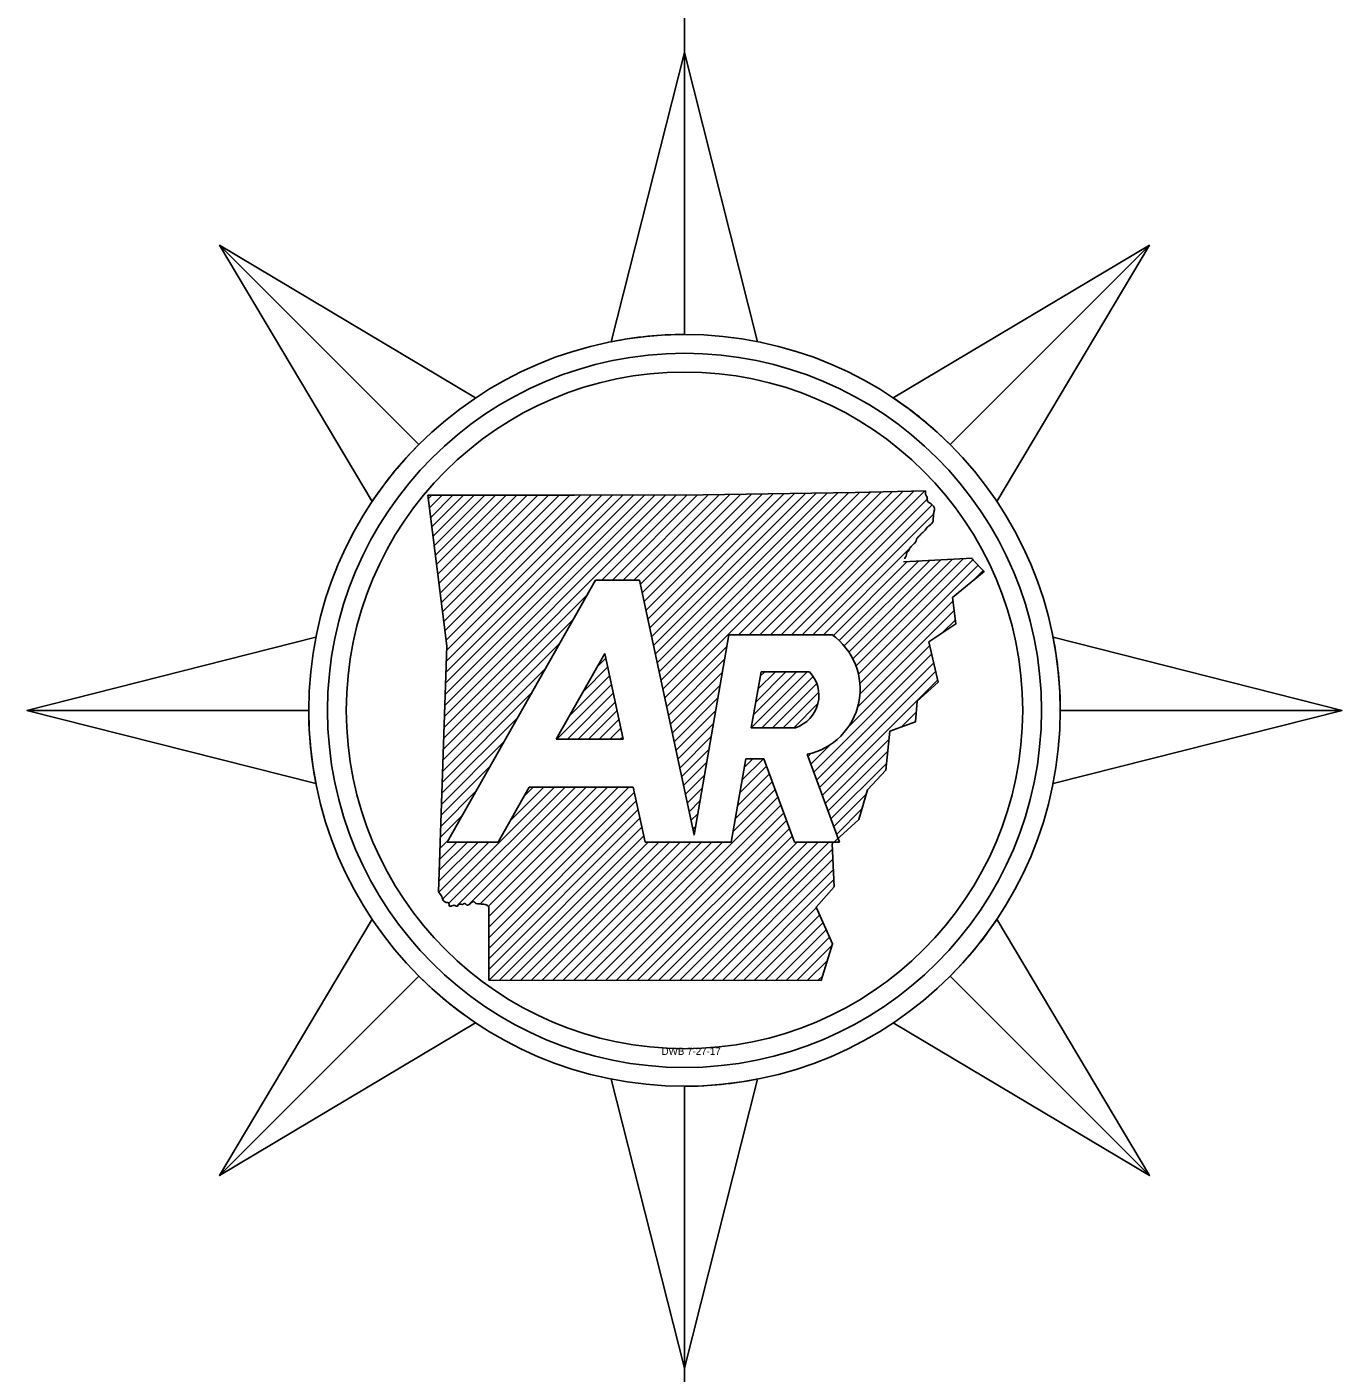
# Model space of a CAD drawing. Extents: x 1368042 to 1371376, y 380392 to 382637.
# Drawn here: x 1370557.8 to 1370680.3, y 381249.8 to 381375.2 of the extents above; entities that cross this region are included whole.
import ezdxf

# ---------------------------------------------------------------- set-up
doc = ezdxf.new("R2010")
doc.units = 0
doc.layers.add('R_Draft', color=7, linetype='Continuous')
doc.layers.add('R_Water Annot', color=7, linetype='Continuous')

msp = doc.modelspace()

# ---------------------------------------------------------------- linework, layer by layer
at = {"layer": 'R_Draft'}
for p, q in [((1370619.08, 381488.53), (1370619.08, 381350.36)), ((1370619.08, 381372.78), (1370612.26, 381345.86)), ((1370619.08, 381346.53), (1370619.08, 381372.78)), ((1370575.77, 381354.84), (1370594.33, 381336.28)), ((1370594.33, 381336.28), (1370575.77, 381354.84)), ((1370575.77, 381354.84), (1370589.98, 381330.99)), ((1370662.39, 381354.84), (1370638.53, 381340.63)), ((1370643.83, 381336.28), (1370662.39, 381354.84)), ((1370643.83, 381336.28), (1370662.39, 381354.84)), ((1370596.97, 381299.27), (1370610.78, 381323.66)), ((1370610.78, 381323.66), (1370614.89, 381323.66)), ((1370623.22, 381318.57), (1370632.81, 381318.57)), ((1370680.33, 381311.53), (1370653.41, 381318.35)), ((1370607.13, 381308.85), (1370611.65, 381316.82)), ((1370626.21, 381315.13), (1370630.71, 381315.13)), ((1370557.83, 381311.53), (1370584.08, 381311.53)), ((1370584.08, 381311.53), (1370557.83, 381311.53)), ((1370557.83, 381311.53), (1370584.75, 381304.72)), ((1370654.08, 381311.53), (1370680.33, 381311.53)), ((1370654.08, 381311.53), (1370680.33, 381311.53)), ((1370625.3, 381309.92), (1370629.41, 381309.92)), ((1370607.13, 381308.85), (1370613.36, 381308.85)), ((1370630.52, 381307.44), (1370633.53, 381299.27)), ((1370626.46, 381307.03), (1370624.79, 381307.03)), ((1370629.32, 381299.27), (1370626.46, 381307.03)), ((1370604.61, 381304.39), (1370601.71, 381299.27)), ((1370614.31, 381304.39), (1370604.61, 381304.39)), ((1370601.71, 381299.27), (1370596.97, 381299.27)), ((1370623.44, 381299.27), (1370615.41, 381299.27)), ((1370633.53, 381299.27), (1370629.32, 381299.27)), ((1370662.39, 381268.22), (1370648.17, 381292.08)), ((1370575.77, 381268.22), (1370594.33, 381286.79)), ((1370594.33, 381286.79), (1370575.77, 381268.22)), ((1370643.83, 381286.79), (1370662.39, 381268.22)), ((1370643.83, 381286.79), (1370662.39, 381268.22)), ((1370575.77, 381268.22), (1370599.62, 381282.44)), ((1370619.08, 381250.28), (1370625.89, 381277.2)), ((1370619.08, 381276.53), (1370619.08, 381276.54)), ((1370619.08, 381276.53), (1370619.08, 381164.49)), ((1370619.08, 381276.53), (1370619.08, 381250.28))]:
    msp.add_line(p, q, dxfattribs=at)
for points in [[(1370612.26, 381345.86), (1370619.08, 381372.78), (1370625.89, 381345.86)], [(1370589.98, 381330.99), (1370575.77, 381354.84), (1370599.62, 381340.63)], [(1370638.53, 381340.63), (1370662.39, 381354.84), (1370648.17, 381330.99)], [(1370595.18, 381331.57), (1370608.84, 381331.56), (1370620.83, 381331.59), (1370634.97, 381331.81), (1370641.52, 381331.96)], [(1370596.17, 381294.62), (1370596.93, 381317.53), (1370595.18, 381331.57)], [(1370645.81, 381325.68), (1370646.99, 381324.45), (1370644.05, 381322.03), (1370644.36, 381319.58), (1370641.84, 381317.91), (1370642.7, 381314.16), (1370640.75, 381312.38), (1370640.58, 381310.45), (1370638.21, 381309.59), (1370637.84, 381305.95), (1370636.14, 381304.13), (1370635.32, 381301.38), (1370632.84, 381299.11), (1370633.03, 381295.11), (1370631.34, 381293.22), (1370632.88, 381289.79), (1370631.81, 381286.37)], [(1370639.49, 381325.36), (1370645.9, 381325.69)], [(1370614.89, 381323.66), (1370619.97, 381299.93), (1370623.22, 381318.57)], [(1370584.75, 381304.72), (1370557.83, 381311.53), (1370584.75, 381318.35)], [(1370653.41, 381318.35), (1370680.33, 381311.53), (1370653.41, 381304.72)], [(1370611.65, 381316.82), (1370613.36, 381308.85)], [(1370625.3, 381309.92), (1370626.21, 381315.13)], [(1370624.79, 381307.03), (1370623.44, 381299.27)], [(1370615.41, 381299.27), (1370614.31, 381304.39)], [(1370631.81, 381286.37), (1370600.86, 381286.42), (1370600.84, 381293.26)], [(1370599.62, 381282.44), (1370575.77, 381268.22), (1370589.98, 381292.08)], [(1370648.17, 381292.08), (1370662.39, 381268.22), (1370638.53, 381282.44)], [(1370625.89, 381277.2), (1370619.08, 381250.28), (1370612.26, 381277.2)]]:
    msp.add_lwpolyline(points, dxfattribs=at)
for radius in [35, 31.5]:
    msp.add_circle((1370619.08, 381311.53), radius, dxfattribs=at)
for centre, radius, start, end in [((1370619.08, 381311.53), 35, 90, 101.2291), ((1370619.08, 381311.53), 35, 45, 56.2291), ((1370619.08, 381311.53), 35, 135, 146.2291), ((1370629.24, 381313.51), 6.2, 281.8626, 54.8705), ((1370619.08, 381311.53), 35, 0, 11.2291), ((1370628.43, 381312.93), 3.17, 288.1268, 43.8902), ((1370619.08, 381311.53), 35, 180, 191.2291), ((1370619.08, 381311.53), 35, 315, 326.2291), ((1370619.08, 381311.53), 35, 225, 236.2291), ((1370619.08, 381311.53), 35, 270, 281.2291)]:
    msp.add_arc(centre, radius, start, end, dxfattribs=at)
for points in [[(1370641.52, 381331.96), (1370641.56, 381331.59), (1370641.68, 381331.39), (1370641.7, 381331.04), (1370641.84, 381330.89), (1370642.09, 381330.73), (1370642.3, 381330.49), (1370642.36, 381330.2), (1370642.29, 381329.91), (1370642.27, 381329.58), (1370642.24, 381329.29), (1370642.19, 381329.03), (1370641.98, 381328.82), (1370641.79, 381328.66), (1370641.61, 381328.49), (1370641.49, 381328.3), (1370641.27, 381328.1), (1370641.05, 381327.89), (1370640.87, 381327.7), (1370640.69, 381327.46), (1370640.61, 381327.2), (1370640.41, 381327.02), (1370640.26, 381326.85), (1370640.06, 381326.62), (1370639.96, 381326.39), (1370639.76, 381326.13), (1370639.72, 381325.88), (1370639.59, 381325.67), (1370639.59, 381325.64)], [(1370600.84, 381293.26), (1370600.88, 381293.24), (1370600.72, 381293.35), (1370600.5, 381293.46), (1370600.25, 381293.48), (1370599.94, 381293.52), (1370599.68, 381293.54), (1370599.41, 381293.72), (1370599.12, 381293.54), (1370598.8, 381293.4), (1370598.61, 381293.55), (1370598.37, 381293.45), (1370598.2, 381293.5), (1370597.9, 381293.3), (1370597.62, 381293.38), (1370597.42, 381293.32), (1370597.17, 381293.33), (1370597.12, 381293.61), (1370596.87, 381293.65), (1370596.66, 381293.77), (1370596.52, 381294.07), (1370596.42, 381294.3), (1370596.17, 381294.62)]]:
    msp.add_spline(points, degree=3, dxfattribs=at)
at = {"layer": 'R_Water Annot'}
for p, q in [((1370595.22, 381331.26), (1370595.53, 381331.57)), ((1370595.33, 381330.38), (1370596.52, 381331.57)), ((1370595.44, 381329.5), (1370597.51, 381331.57)), ((1370595.55, 381328.62), (1370598.5, 381331.57)), ((1370595.66, 381327.74), (1370599.49, 381331.57)), ((1370595.77, 381326.86), (1370600.48, 381331.57)), ((1370595.88, 381325.98), (1370601.47, 381331.57)), ((1370595.99, 381325.1), (1370602.46, 381331.56)), ((1370596.1, 381324.22), (1370603.45, 381331.56)), ((1370596.21, 381323.34), (1370604.43, 381331.56)), ((1370596.32, 381322.46), (1370605.42, 381331.56)), ((1370596.43, 381321.58), (1370606.41, 381331.56)), ((1370596.54, 381320.7), (1370607.4, 381331.56)), ((1370596.65, 381319.82), (1370608.39, 381331.56)), ((1370596.68, 381309.95), (1370618.31, 381331.58)), ((1370596.71, 381310.97), (1370617.32, 381331.58)), ((1370596.75, 381312), (1370616.33, 381331.58)), ((1370596.76, 381318.94), (1370609.38, 381331.56)), ((1370596.78, 381313.02), (1370615.34, 381331.57)), ((1370596.82, 381314.05), (1370614.34, 381331.57)), ((1370596.85, 381315.07), (1370613.35, 381331.57)), ((1370596.87, 381318.06), (1370610.38, 381331.56)), ((1370596.88, 381316.09), (1370612.36, 381331.57)), ((1370596.92, 381317.12), (1370611.37, 381331.57)), ((1370611.38, 381323.66), (1370619.3, 381331.58)), ((1370612.37, 381323.66), (1370620.3, 381331.59)), ((1370613.36, 381323.66), (1370621.29, 381331.59)), ((1370614.35, 381323.66), (1370622.3, 381331.61)), ((1370614.97, 381323.29), (1370623.31, 381331.62)), ((1370615.14, 381322.47), (1370624.31, 381331.64)), ((1370615.32, 381321.66), (1370625.32, 381331.66)), ((1370615.49, 381320.84), (1370626.32, 381331.67)), ((1370615.67, 381320.03), (1370627.33, 381331.69)), ((1370615.84, 381319.21), (1370628.33, 381331.7)), ((1370616.01, 381318.39), (1370629.34, 381331.72)), ((1370616.19, 381317.58), (1370630.34, 381331.73)), ((1370616.36, 381316.76), (1370631.35, 381331.75)), ((1370616.54, 381315.95), (1370632.36, 381331.77)), ((1370616.71, 381315.13), (1370633.36, 381331.78)), ((1370616.89, 381314.32), (1370634.37, 381331.8)), ((1370617.06, 381313.5), (1370635.38, 381331.82)), ((1370617.24, 381312.69), (1370636.39, 381331.84)), ((1370624.11, 381318.57), (1370637.4, 381331.86)), ((1370625.1, 381318.57), (1370638.42, 381331.89)), ((1370626.09, 381318.57), (1370639.43, 381331.91)), ((1370627.08, 381318.57), (1370640.44, 381331.93)), ((1370628.07, 381318.57), (1370641.46, 381331.96)), ((1370629.06, 381318.57), (1370641.68, 381331.19)), ((1370630.05, 381318.57), (1370642.15, 381330.68)), ((1370631.04, 381318.57), (1370642.28, 381329.81)), ((1370632.03, 381318.57), (1370640.02, 381326.56)), ((1370632.93, 381318.48), (1370639.83, 381325.38)), ((1370633.47, 381318.03), (1370640.87, 381325.43)), ((1370633.96, 381317.53), (1370641.92, 381325.49)), ((1370634.38, 381316.96), (1370642.96, 381325.54)), ((1370634.75, 381316.34), (1370644, 381325.59)), ((1370635.05, 381315.65), (1370645.05, 381325.65)), ((1370635.28, 381314.89), (1370645.99, 381325.6)), ((1370635.42, 381314.04), (1370646.45, 381325.07)), ((1370646.01, 381323.64), (1370646.91, 381324.54)), ((1370596.65, 381308.93), (1370610, 381322.28)), ((1370635.42, 381313.05), (1370644.09, 381321.72)), ((1370596.61, 381307.9), (1370608.71, 381320)), ((1370635.21, 381311.85), (1370644.2, 381320.84)), ((1370643.09, 381318.74), (1370644.31, 381319.96)), ((1370596.58, 381306.88), (1370607.42, 381317.72)), ((1370617.41, 381311.87), (1370623.03, 381317.49)), ((1370634.35, 381310), (1370641.92, 381317.57)), ((1370610.95, 381315.58), (1370611.75, 381316.38)), ((1370617.59, 381311.06), (1370622.82, 381316.29)), ((1370631.13, 381305.79), (1370642.1, 381316.76)), ((1370631.39, 381305.07), (1370642.29, 381315.96)), ((1370596.54, 381305.85), (1370606.13, 381315.44)), ((1370608.36, 381311.02), (1370612.09, 381314.75)), ((1370609.66, 381313.3), (1370611.92, 381315.56)), ((1370617.76, 381310.24), (1370622.61, 381315.09)), ((1370625.3, 381309.92), (1370630.51, 381315.13)), ((1370625.51, 381311.12), (1370629.52, 381315.13)), ((1370625.72, 381312.31), (1370628.53, 381315.13)), ((1370625.92, 381313.51), (1370627.54, 381315.13)), ((1370626.13, 381314.71), (1370626.55, 381315.13)), ((1370626.29, 381309.92), (1370631.06, 381314.69)), ((1370631.66, 381304.34), (1370642.47, 381315.15)), ((1370607.18, 381308.85), (1370612.27, 381313.93)), ((1370617.93, 381309.42), (1370622.4, 381313.89)), ((1370627.28, 381309.92), (1370631.4, 381314.04)), ((1370631.93, 381303.62), (1370642.66, 381314.35)), ((1370596.51, 381304.83), (1370604.84, 381313.16)), ((1370608.17, 381308.85), (1370612.44, 381313.12)), ((1370609.16, 381308.85), (1370612.62, 381312.3)), ((1370618.11, 381308.61), (1370622.19, 381312.69)), ((1370628.27, 381309.92), (1370631.58, 381313.23)), ((1370629.26, 381309.92), (1370631.5, 381312.16)), ((1370610.15, 381308.85), (1370612.79, 381311.49)), ((1370618.28, 381307.79), (1370621.98, 381311.49)), ((1370639.27, 381309.98), (1370640.66, 381311.36)), ((1370596.48, 381303.81), (1370603.54, 381310.87)), ((1370611.14, 381308.85), (1370612.97, 381310.67)), ((1370612.13, 381308.85), (1370613.14, 381309.86)), ((1370618.46, 381306.98), (1370621.77, 381310.3)), ((1370596.44, 381302.78), (1370602.25, 381308.59)), ((1370613.12, 381308.85), (1370613.32, 381309.04)), ((1370618.63, 381306.16), (1370621.57, 381309.1)), ((1370630.86, 381306.51), (1370632.74, 381308.4)), ((1370632.2, 381302.9), (1370638.13, 381308.84)), ((1370618.81, 381305.35), (1370621.36, 381307.9)), ((1370630.59, 381307.23), (1370630.89, 381307.54)), ((1370632.46, 381302.17), (1370638.02, 381307.73)), ((1370596.41, 381301.76), (1370600.96, 381306.31)), ((1370618.98, 381304.53), (1370621.15, 381306.7)), ((1370624.24, 381303.85), (1370626.72, 381306.33)), ((1370624.45, 381305.05), (1370626.43, 381307.03)), ((1370624.66, 381306.25), (1370625.44, 381307.03)), ((1370632.73, 381301.45), (1370637.91, 381306.63)), ((1370619.16, 381303.72), (1370620.94, 381305.5)), ((1370623.82, 381301.45), (1370627.25, 381304.88)), ((1370624.03, 381302.65), (1370626.98, 381305.6)), ((1370596.37, 381300.73), (1370599.67, 381304.03)), ((1370596.56, 381293.99), (1370606.96, 381304.39)), ((1370597.14, 381293.58), (1370607.95, 381304.39)), ((1370597.85, 381293.31), (1370608.94, 381304.39)), ((1370599.03, 381293.49), (1370609.93, 381304.39)), ((1370600.04, 381293.51), (1370610.92, 381304.39)), ((1370600.81, 381293.29), (1370611.91, 381304.39)), ((1370600.84, 381292.34), (1370612.9, 381304.39)), ((1370600.85, 381291.35), (1370613.89, 381304.39)), ((1370600.85, 381290.36), (1370614.41, 381303.92)), ((1370602.84, 381301.26), (1370605.97, 381304.39)), ((1370604.13, 381303.54), (1370604.98, 381304.39)), ((1370610.76, 381286.41), (1370627.78, 381303.44)), ((1370619.33, 381302.9), (1370620.73, 381304.3)), ((1370623.61, 381300.26), (1370627.52, 381304.16)), ((1370633, 381300.73), (1370636.03, 381303.76)), ((1370600.85, 381289.37), (1370614.59, 381303.11)), ((1370600.85, 381288.39), (1370614.76, 381302.29)), ((1370611.75, 381286.41), (1370628.05, 381302.71)), ((1370619.5, 381302.09), (1370620.52, 381303.1)), ((1370633.26, 381300.01), (1370635.61, 381302.35)), ((1370596.34, 381299.71), (1370598.37, 381301.74)), ((1370600.86, 381287.4), (1370614.93, 381301.48)), ((1370612.73, 381286.41), (1370628.32, 381301.99)), ((1370613.72, 381286.4), (1370628.59, 381301.27)), ((1370619.68, 381301.27), (1370620.31, 381301.9)), ((1370600.87, 381286.42), (1370615.11, 381300.66)), ((1370601.86, 381286.42), (1370615.28, 381299.84)), ((1370614.71, 381286.4), (1370628.85, 381300.54)), ((1370615.7, 381286.4), (1370629.12, 381299.82)), ((1370619.85, 381300.46), (1370620.1, 381300.7)), ((1370596.19, 381294.61), (1370600.85, 381299.27)), ((1370596.21, 381295.62), (1370599.86, 381299.27)), ((1370596.24, 381296.64), (1370598.87, 381299.27)), ((1370596.27, 381297.66), (1370597.88, 381299.27)), ((1370596.31, 381298.69), (1370597.08, 381299.46)), ((1370602.85, 381286.42), (1370615.7, 381299.27)), ((1370603.84, 381286.42), (1370616.69, 381299.27)), ((1370604.83, 381286.42), (1370617.68, 381299.27)), ((1370605.82, 381286.42), (1370618.67, 381299.27)), ((1370606.8, 381286.42), (1370619.66, 381299.27)), ((1370607.79, 381286.41), (1370620.65, 381299.27)), ((1370608.78, 381286.41), (1370621.64, 381299.27)), ((1370609.77, 381286.41), (1370622.63, 381299.27)), ((1370616.69, 381286.4), (1370629.56, 381299.27)), ((1370617.68, 381286.4), (1370630.55, 381299.27)), ((1370618.66, 381286.4), (1370631.54, 381299.27)), ((1370619.65, 381286.39), (1370632.53, 381299.27)), ((1370620.64, 381286.39), (1370632.86, 381298.61)), ((1370621.63, 381286.39), (1370632.91, 381297.67)), ((1370622.62, 381286.39), (1370632.95, 381296.72)), ((1370623.61, 381286.39), (1370633, 381295.78)), ((1370624.59, 381286.39), (1370631.37, 381293.16)), ((1370625.58, 381286.38), (1370631.68, 381292.48)), ((1370626.57, 381286.38), (1370631.98, 381291.79)), ((1370627.56, 381286.38), (1370632.29, 381291.11)), ((1370628.55, 381286.38), (1370632.59, 381290.42)), ((1370629.54, 381286.38), (1370632.85, 381289.69)), ((1370630.52, 381286.38), (1370632.4, 381288.25)), ((1370631.51, 381286.37), (1370631.95, 381286.81))]:
    msp.add_line(p, q, dxfattribs=at)
msp.add_circle((1370619.08, 381311.53), 33.25, dxfattribs=at)

# ---------------------------------------------------------------- texts
at = {"layer": 'R_Draft'}
msp.add_text('DWB 7-27-17', height=0.6806, dxfattribs=at).set_placement((1370616.94, 381279.45))

doc.saveas('drawing.dxf')
